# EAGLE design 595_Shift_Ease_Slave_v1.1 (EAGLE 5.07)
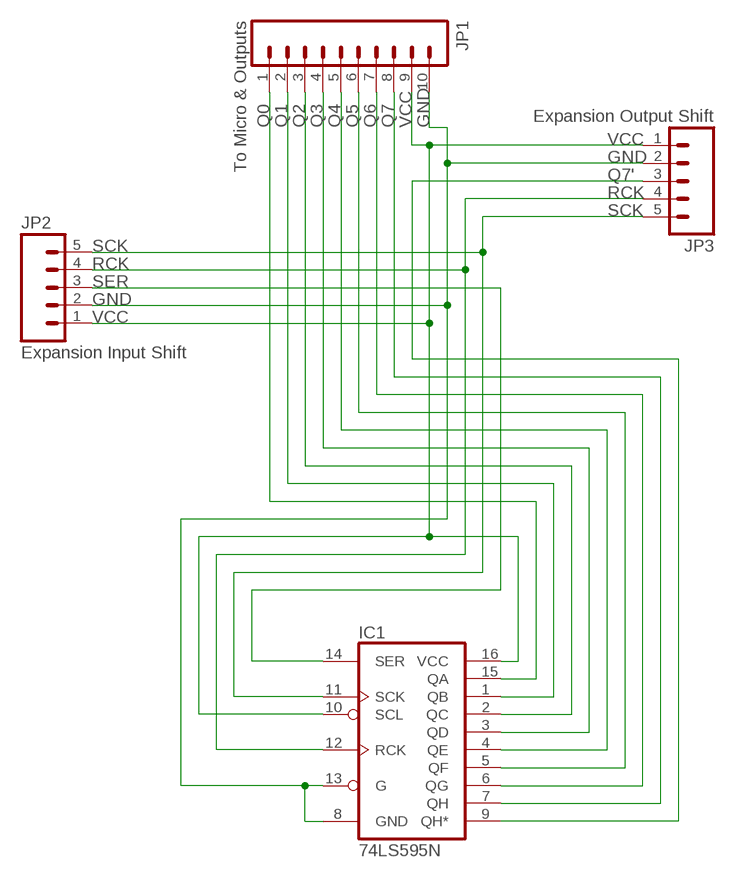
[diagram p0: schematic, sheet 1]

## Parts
IC1  74LS595N  [DIL16]
JP1  To Micro & Outputs  M101X10_F_H  [1X10_F_H]
JP2  Expansion Input Shift  M051X05_M_H  [1X05_M_H]
JP3  Expansion Output Shift  M051X05_F_H  [1X05_F_H]

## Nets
GND: IC1.8(GND) IC1.13(G) JP1.10 JP2.2 JP3.2
Q0: IC1.15(QA) JP1.1
Q1: IC1.1(QB) JP1.2
Q2: IC1.2(QC) JP1.3
Q3: IC1.3(QD) JP1.4
Q4: IC1.4(QE) JP1.5
Q5: IC1.5(QF) JP1.6
Q6: IC1.6(QG) JP1.7
Q7: IC1.7(QH) JP1.8
Q7': IC1.9(QH*) JP3.3
RCK: IC1.12(RCK) JP2.4 JP3.4
SCK: IC1.11(SCK) JP2.5 JP3.5
SER: IC1.14(SER) JP2.3
VCC: IC1.10(SCL) IC1.16(VCC) JP1.9 JP2.1 JP3.1

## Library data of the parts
IC1 = SparkFun:74*595: 8-bit SHIFT REGISTER, output latch
JP1 = SparkFun:M10: Header 10 Standard 10-pin 0.1" header. Use with straight break away headers (SKU : PRT-00116), right angle break away headers (PRT-00553), swiss pins (PRT-00743), machine pins (PRT-00117), and female headers (PRT-00115).
JP2 JP3 = SparkFun:M05: Header 5 Standard 5-pin 0.1" header. Use with straight break away headers (SKU : PRT-00116), right angle break away headers (PRT-00553), swiss pins (PRT-00743), machine pins (PRT-00117), and female headers (PRT-00115). Molex polarized connector foot print use with SKU : PRT-08230 with associated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

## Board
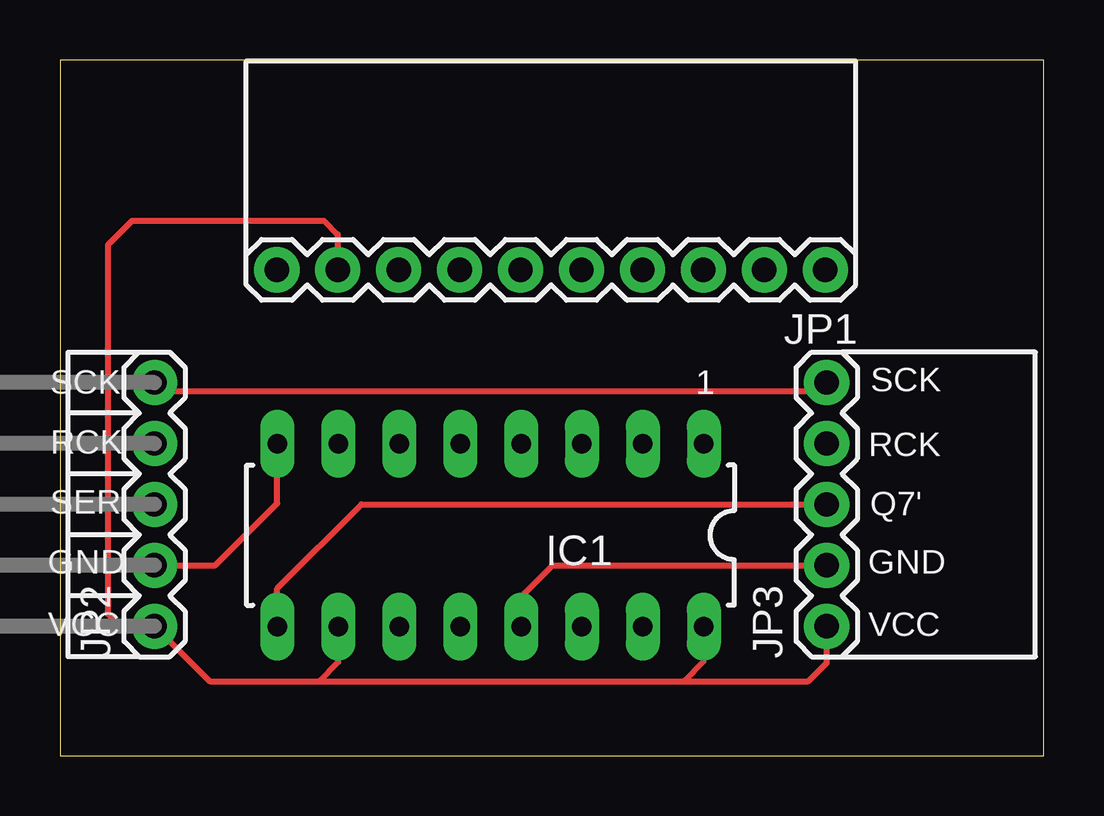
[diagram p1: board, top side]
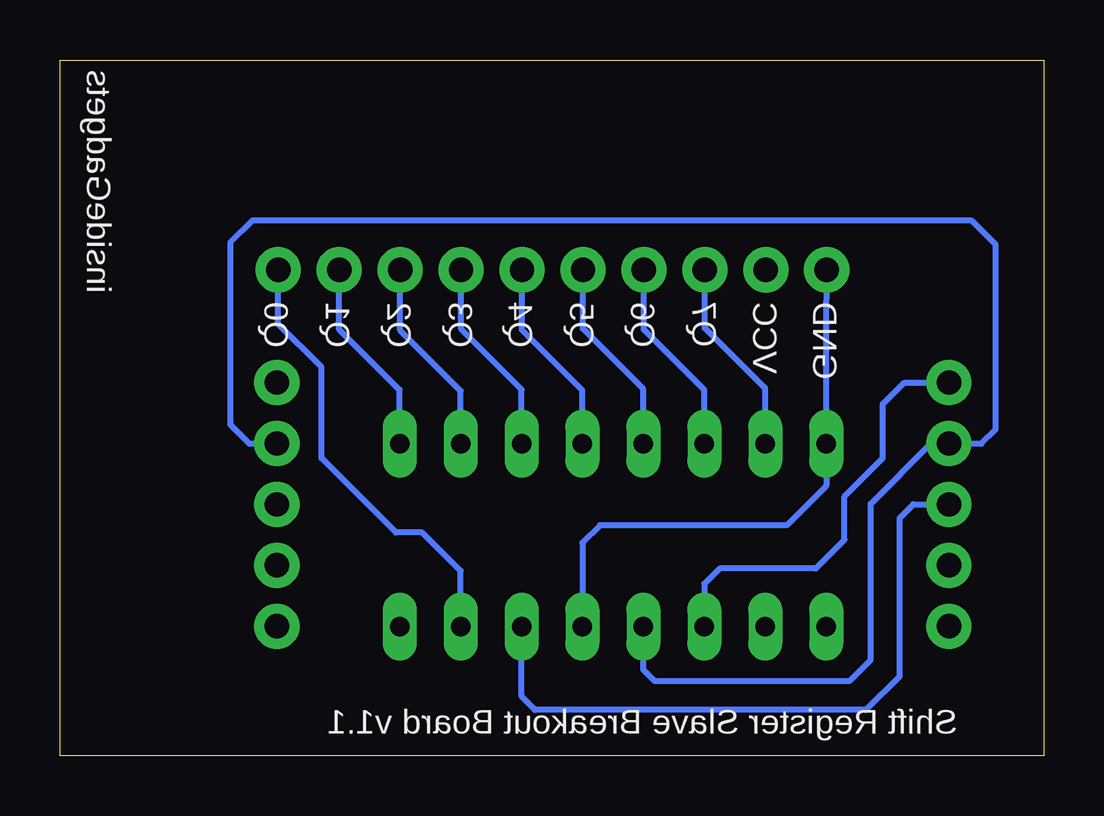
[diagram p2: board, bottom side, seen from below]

Size 41 x 29 mm. Coordinates in mm from the lower left corner, seen from the top.
Outline: 0,0 41,0 41,29 0,29 0,0
Copper layers (1*16): Top 0.035mm / dielectric 1.5mm / Bottom 0.035mm
Design rules "SparkFun": minimum track width 8mil, minimum drill 20mil, track to track 8mil, track to pad 8mil, pad to pad 8mil, via to via 8mil, smd to smd 8mil, copper to edge 10mil, drill to drill 8mil, minimum pad ring 12mil, minimum via ring 10mil, stop-mask expansion 4mil, vias tented up to drill 25mil, thermal gap 10mil

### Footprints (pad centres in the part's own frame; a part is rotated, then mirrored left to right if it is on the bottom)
DIL16 = drill 0.813 long: 1 -8.89,-3.81; 2 -6.35,-3.81; 3 -3.81,-3.81; 4 -1.27,-3.81; 5 1.27,-3.81; 6 3.81,-3.81; 7 6.35,-3.81; 8 8.89,-3.81; 9 8.89,3.81; 10 6.35,3.81; 11 3.81,3.81; 12 1.27,3.81; 13 -1.27,3.81; 14 -3.81,3.81; 15 -6.35,3.81; 16 -8.89,3.81
1X10_F_H = drill 1.016 pad 1.88 round: 1 0,0; 2 2.54,0; 3 5.08,0; 4 7.62,0; 5 10.16,0; 6 12.7,0; 7 15.24,0; 8 17.78,0; 9 20.32,0; 10 22.86,0
1X05_M_H = drill 1.016 pad 1.88 round: 1 0,0; 2 2.54,0; 3 5.08,0; 4 7.62,0; 5 10.16,0
1X05_F_H = drill 1.016 pad 1.88 round: 1 0,0; 2 2.54,0; 3 5.08,0; 4 7.62,0; 5 10.16,0

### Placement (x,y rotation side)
IC1  17.95,9.19 180 top
JP1  31.9,20.25 180 top
JP2  3.94,5.39 90 top
JP3  31.96,5.39 90 top

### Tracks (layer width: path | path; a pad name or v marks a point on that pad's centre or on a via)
GND
  Top 0.254: JP2.2 6.47,7.93 9.06,10.52 IC1.8 | JP3.2 20.53,7.93 19.22,6.62 IC1.13
  Bottom 0.254: IC1.13 19.22,8.88 18.5,9.6 10.7,9.6 9.06,11.24 IC1.8 9.06,17.73 JP1.10
Q0
  Bottom 0.254: IC1.15 24.3,7.7 25.9,9.3 27,9.3 30.1,12.4 30.1,16.2 31.9,18 JP1.1
Q1
  Bottom 0.254: IC1.1 26.84,15.24 29.36,17.76 JP1.2
Q2
  Bottom 0.254: IC1.2 24.3,15.2 26.82,17.72 JP1.3
Q3
  Bottom 0.254: IC1.3 21.76,15.26 24.28,17.78 JP1.4
Q4
  Bottom 0.254: IC1.4 19.22,15.22 21.74,17.74 JP1.5
Q5
  Bottom 0.254: IC1.5 16.68,15.28 19.2,17.8 JP1.6
Q6
  Bottom 0.254: IC1.6 14.14,15.24 16.66,17.76 JP1.7
Q7
  Bottom 0.254: IC1.7 11.6,15.3 14.12,17.82 JP1.8
Q7'
  Top 0.254: JP3.3 12.57,10.47 9.06,6.96 IC1.9
RCK
  Bottom 0.254: JP3.4 33.11,13.01 33.9,13.8 33.9,21.4 33,22.3 3,22.3 2,21.3 2,13.6 2.59,13.01 JP2.4 4.69,13.01 7.2,10.5 7.2,4 8.1,3.1 16.2,3.1 16.68,3.58 IC1.12
SCK
  Top 0.254: JP2.5 4.29,15.2 31.61,15.2 JP3.5
  Bottom 0.254: JP2.5 5.8,15.55 6.7,14.65 6.7,12.4 8.3,10.8 8.3,9 9.5,7.8 13.5,7.8 14.14,7.16 IC1.11
SER
  Bottom 0.254: JP2.3 5.43,10.47 6,9.9 6,3.3 7.4,1.9 21.2,1.9 21.76,2.46 IC1.14
VCC
  Top 0.254: 10.8,3.1 6.23,3.1 JP2.1 2.51,5.39 2,5.9 2,21.3 3,22.3 11,22.3 11.58,21.72 JP1.9 | 10.8,3.1 26,3.1 | 26,3.1 31.2,3.1 31.96,3.86 JP3.1 | IC1.10 11.6,3.9 10.8,3.1 | IC1.16 26.84,3.94 26,3.1

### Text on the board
tPlace: SCK | 1 | SCK | RCK | RCK | SER | Q7' | GND | GND | VCC | VCC
bPlace: insideGadgets | GND | VCC | Q7 | Q6 | Q5 | Q4 | Q3 | Q2 | Q1 | Q0 | Shift Register Slave Breakout Board v1.1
